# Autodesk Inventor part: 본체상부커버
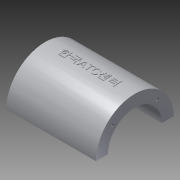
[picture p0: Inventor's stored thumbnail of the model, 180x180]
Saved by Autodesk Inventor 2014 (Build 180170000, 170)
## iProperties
Created: 2015-12
Part Number: 본체상부커버
Material: 알루미늄 6061
Document SubType Name: Modeling
Designer: mduedu
Density: 2.71 g/cm^3
Mass: 175.162 g
Surface Area: 166.445 cm^2
Volume: 64.6353 cm^3
Appearance: 알루미늄 - 평지
Author: mduedu
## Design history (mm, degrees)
sketch "스케치1"
  geometry: L1 (45, 40)-(-45, 40); L2 (-45, 40)-(-45, -40); L3 (-45, -40)-(45, -40); L4 (45, -40)-(45, 40); L5 (45, 40)-(-45, -40); L6 (-45, 40)-(45, -40); 2 further points
  constraints: 12 end point, 2 midpoint, 2 parallel, 1 coincident, 1 horizontal, 1 perpendicular, 3 other
  dimensions: "d0" = 90 distance of L2.end L3.end; "d2" = 80 distance of L1.end L2.end
extrude "돌출1" new body sketch "스케치1" distance "d3" = 10; taper "d4" = 0 deg
sketch "스케치2"
  geometry: C1 r 32.5 at (80, 0); 1 further point
  constraints: 1 centre point
  dimensions: "d5" = 65 diameter of C1; "d116" = 80 distance of point (0, 0) C1.centre
extrude "돌출2" join sketch "스케치2" stored distance "d7" = 75; taper "d8" = 0 deg
sketch "스케치3"
  geometry: L1 (-27.5, -20)-(27.5, -20); L2 (27.5, -20)-(27.5, 20); L3 (27.5, 20)-(-27.5, 20); L4 (-27.5, 20)-(-27.5, -20); L5 (-27.5, -20)-(27.5, 20); L6 (27.5, -20)-(-27.5, 20); 1 further point
  constraints: 12 end point, 2 midpoint, 2 parallel, 1 horizontal, 1 perpendicular
  dimensions: "d9" = 55 distance of L2.end L3.end; "d11" = 40 distance of L1.end L2.end
extrude "돌출3" new body sketch "스케치3" stored distance "d12" = 75; taper "d13" = 0 deg
fillet "모깎기1"
fillet "모깎기2"
feature "결합1"
  node "솔리드2"
sketch "스케치4"
  geometry: L1 (-37.5, 47.5)-(37.5, 47.5) reference; L2 (32.5, 47.5)-(40.208, 10); L3 (37.5, 47.5)-(37.5, 112.5) reference; L4 (60.208, 0)-(60.208, 10) reference; L5 (60.208, 10)-(-60.208, 10) reference; 1 further point
  constraints: 2 end point, 2 point on line
  dimensions: "d15" = 5 distance from line of L2.start L3; "d117" = 20 distance from line of L2.end L4
sketch "스케치5"
  geometry: L1 (10, 35.208)-(56.729, 22.687); L2 (0, 60.208)-(10, 60.208) reference; L3 (10, -60.208)-(10, 60.208) reference; 2 further points
  constraints: 2 end point, 1 point on line, 2 other
  dimensions: "d118" = 25 distance from line of L1.start L2; "d119" = 75 deg angle of L1 L3
feature "리브1" dims "d19" = 1, "d20" = 6, "d21" = 0, "d22" = 0, "d23" = 1, "d24" = 1
feature "리브2" dims "d25" = 1, "d26" = 6, "d27" = 0, "d28" = 0, "d29" = 1, "d30" = 1
fillet "모깎기4" dims "d31" = 2
fillet "모깎기5" dims "d32" = 2
fillet "모깎기6" dims "d33" = 2
sketch "스케치6"
  geometry: L1 (0, 0)-(-32.88, 32.88); L2 (0, 0)-(-46.5, 0); A1 r 46.5 centre (0, 0) between (-32.88, 32.88) and (-46.5, 0); 5 further points
  constraints: 4 end point, 2 coincident, 2 point on circle, 1 centre point, 1 horizontal, 5 other
  dimensions: "d120" = 93 diameter of A1; "d122" = 45 deg angle of L1 L2; "d126" = 360 deg dimension on point (0, 0) point (-32.88, 32.88) (derived)
hole "구멍1" sketch "스케치6" at (-32.88, 32.88), (-32.88, -32.88), (32.88, -32.88), (32.88, 32.88) diameter "d34" = 7; stored, may be unused: countersink angle "d38" = 90 deg, drill point angle "d40" = 118 deg; dims "d35" = 6, "d36" = 12, "d37" = 3, "d39" = 8
fillet "모깎기13" dims "d131" = 3
hole "구멍2" diameter "d44" = 45; stored, may be unused: countersink angle "d48" = 90 deg, drill point angle "d50" = 118 deg; dims "d42" = 10, "d43" = 10, "d45" = 6, "d46" = 4, "d47" = 2, "d49" = 8
sketch "스케치7" dims "d52" = 26.5
  geometry: L1 (0, 0)-(32.5, 0); L2 (0, 0)-(22.981, 22.981); A1 r 32.5 centre (0, 0) between (32.5, 0) and (22.981, 22.981) reference; 3 further points
  constraints: 4 end point, 2 point on circle, 1 coincident, 1 horizontal, 1 point on line, 3 other
  dimensions: "d51" = 45 deg angle of L2 L1
hole "구멍3" sketch "스케치7" at (18.738, 18.738) diameter "d54" = 2.459; stored, may be unused: countersink angle "d58" = 90 deg, drill point angle "d60" = 118 deg; dims "d55" = 8, "d56" = 4, "d57" = 2, "d59" = 10
sketch "스케치9"
  geometry: L1 (-75, -110)-(75, -110); L2 (75, -110)-(75, 0); L3 (75, 0)-(-75, 0); L4 (-75, 0)-(-75, -110); L5 (-60.208, -80)-(60.208, -80) reference; C1 r 32.5 at (0, 0) reference; 2 further points
  constraints: 8 end point, 2 parallel, 1 coincident, 1 horizontal, 1 midpoint, 1 perpendicular
  dimensions: "d148" = 30 distance between parallel lines of L5 L1; "d159" = 150 distance between parallel lines of L2 L4
extrude "돌출5" cut sketch "스케치9" stored distance "d73" = 0; taper "d74" = 0 deg
node "작업 평면3"
sketch "스케치17" dims "d2" = 80
  geometry: 2 further points
  constraints: 1 coincident, 1 other
feature "엠보싱1" sketch "스케치17" dims "d0" = 90, "d2" = 80, "d150" = 0.5, "d151" = 0
node "솔리드1"
mirror "대칭1"
mirror "대칭2"
pattern_circular "원형 패턴1" dims angle "d62" = 360 deg
mirror "대칭3"
